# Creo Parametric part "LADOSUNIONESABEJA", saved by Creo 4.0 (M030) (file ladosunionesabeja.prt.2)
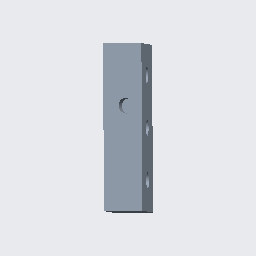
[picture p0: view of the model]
Units: millimeter Newton Second (mmNs); MM, TONNE, SECS

Created from: MMNS_PART_SOLID.PRT

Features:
  1. datum plane "RIGHT"
  2. datum plane "TOP"
  3. datum plane "FRONT"
  4. coordinate system
  5. sketch "Sketch 1"
  6. extrusion "Extrude 1"
  7. pattern "Pattern 1"
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
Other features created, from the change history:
  hole "Hole 1"
  hole "Hole 1 [2]"
  hole "Hole 1 [3]"
  hole "Hole 2"

Surfaces: 10 plane, 4 cylinder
